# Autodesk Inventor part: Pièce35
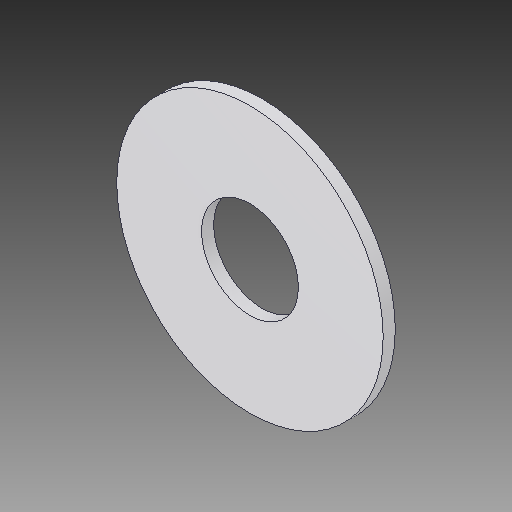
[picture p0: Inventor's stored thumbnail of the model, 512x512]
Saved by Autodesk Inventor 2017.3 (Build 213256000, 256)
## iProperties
Created: 2007-12
Part Number: Pièce35
Material: solidworks materials|Alliage 7079|22
Document SubType Name: Modeling
Designer: ficho
Density: 2.7 g/cm^3
Appearance: 227,227,233
Author: ficho
Sending System: SolidWorks 2009
Last Author: christophe
Last Saved: 2011-02-10
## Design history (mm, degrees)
extrude "Extrusion1"
node "Solide1"
